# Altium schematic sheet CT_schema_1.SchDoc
size 248 x 339 mm
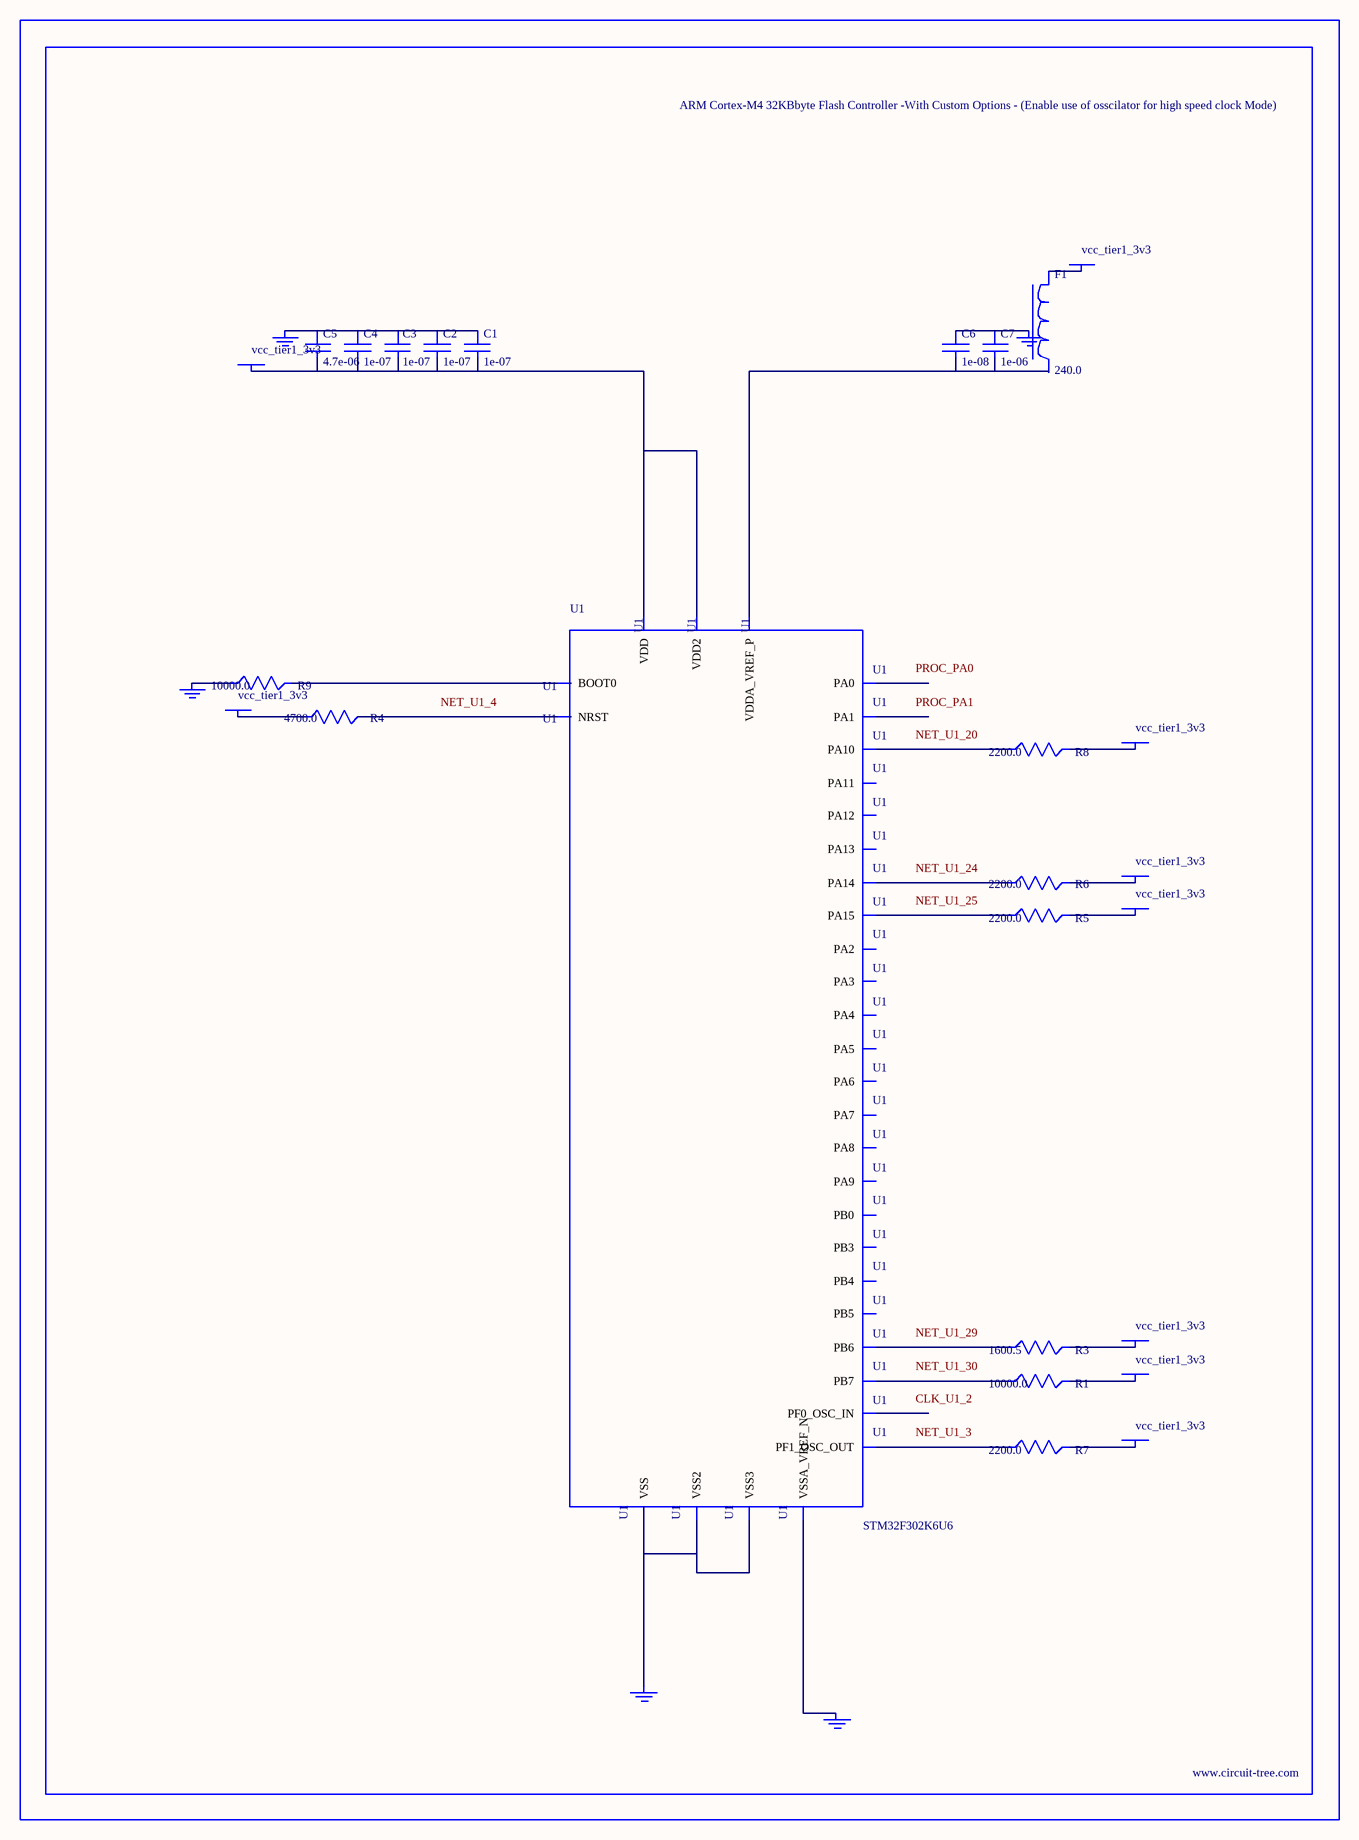
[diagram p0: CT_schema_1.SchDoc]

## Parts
BORDER0  (no value)
C1  1e-07  [C0603]
C2  1e-07  [C0603]
C3  1e-07  [C0603]
C4  1e-07  [C0603]
C5  4.7e-06  [C0603]
C6  1e-08  [C0603]
C7  1e-06  [C0603]
F1  240.0  [L0603]
GND_INSTANCE_0_0  (no value)
GND_INSTANCE_0_1  (no value)
GND_INSTANCE_0_2  (no value)
GND_INSTANCE_0_3  (no value)
GND_INSTANCE_0_4  (no value)
POWER_INSTANCE_0_0  vcc_tier1_3v3
POWER_INSTANCE_0_1  vcc_tier1_3v3
POWER_INSTANCE_0_2  vcc_tier1_3v3
POWER_INSTANCE_0_3  vcc_tier1_3v3
POWER_INSTANCE_0_4  vcc_tier1_3v3
POWER_INSTANCE_0_5  vcc_tier1_3v3
POWER_INSTANCE_0_6  vcc_tier1_3v3
POWER_INSTANCE_0_7  vcc_tier1_3v3
POWER_INSTANCE_0_8  vcc_tier1_3v3
R1  10000.0  [R0603]
R3  1600.5  [R0603]
R4  4700.0  [R0603]
R5  2200.0  [R0603]
R6  2200.0  [R0603]
R7  2200.0  [R0603]
R8  2200.0  [R0603]
R9  10000.0  [R0603]
U1  STM32F302K6U6  [UFQFPN32]

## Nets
NetC1_1: C1.1 C2.1 C3.1 C4.1 C5.1 GND_INSTANCE_0_0.0(GND)
NetC1_2: C1.2 C2.2 C3.2 C4.2 C5.2 POWER_INSTANCE_0_0.0(PWR) U1.1(VDD) U1.17(VDD2)
NetC6_1: C6.1 C7.1 GND_INSTANCE_0_1.0(GND)
NetC6_2: C6.2 C7.2 U1.5(VDDA_VREF_P)
NetF1_1: F1.1 POWER_INSTANCE_0_1.0(PWR)
NetGND_INSTANCE_0_2_0: GND_INSTANCE_0_2.0(GND) U1.6(VSSA_VREF_N)
NetGND_INSTANCE_0_3_0: GND_INSTANCE_0_3.0(GND) R9.1
NetGND_INSTANCE_0_4_0: GND_INSTANCE_0_4.0(GND) U1.16(VSS) U1.32(VSS2) U1.EPAD(VSS3)
NetPOWER_INSTANCE_0_2_0: POWER_INSTANCE_0_2.0(PWR) R7.2
NetPOWER_INSTANCE_0_3_0: POWER_INSTANCE_0_3.0(PWR) R4.1
NetPOWER_INSTANCE_0_4_0: POWER_INSTANCE_0_4.0(PWR) R8.2
NetPOWER_INSTANCE_0_5_0: POWER_INSTANCE_0_5.0(PWR) R6.2
NetPOWER_INSTANCE_0_6_0: POWER_INSTANCE_0_6.0(PWR) R5.2
NetPOWER_INSTANCE_0_7_0: POWER_INSTANCE_0_7.0(PWR) R3.2
NetPOWER_INSTANCE_0_8_0: POWER_INSTANCE_0_8.0(PWR) R1.2
NetR1_1: R1.1 U1.30(PB7)
NetR3_1: R3.1 U1.29(PB6)
NetR4_2: R4.2 U1.4(NRST)
NetR5_1: R5.1 U1.25(PA15)
NetR6_1: R6.1 U1.24(PA14)
NetR7_1: R7.1 U1.3(PF1_OSC_OUT)
NetR8_1: R8.1 U1.20(PA10)
NetR9_2: R9.2 U1.31(BOOT0)

Not connected (* = marked no-connect by the designer): F1 2; U1 2(PF0_OSC_IN) 7(PA0) 8(PA1) 9(PA2) 10(PA3) 11(PA4) 12(PA5) 13(PA6) 14(PA7) 15(PB0) 18(PA8) 19(PA9) 21(PA11) 22(PA12) 23(PA13) 26(PB3) 27(PB4) 28(PB5)

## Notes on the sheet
- Labels drawn without touching a wire or pin: CLK_U1_2, NET_U1_3, NET_U1_4, NET_U1_20, NET_U1_24, NET_U1_25, NET_U1_29, NET_U1_30, PROC_PA0, PROC_PA1

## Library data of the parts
BORDER0 = BORDER_PAGE0
C1-C4 = 06035C104K4Z2A
C5 = GRM188R6YA475KE15D
C6 = 06035C103K4Z2A
C7 = C0603C105K3RACTU
F1 = Z0603C241ASMST
GND_INSTANCE_0_0-GND_INSTANCE_0_4 = GND
POWER_INSTANCE_0_0-POWER_INSTANCE_0_8 = PWR
R1 R9 = RC0603JR-0710KL
R3 = R3
R4 = RC0603JR-074K7L
R5-R8 = RC0603JR-072K2L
